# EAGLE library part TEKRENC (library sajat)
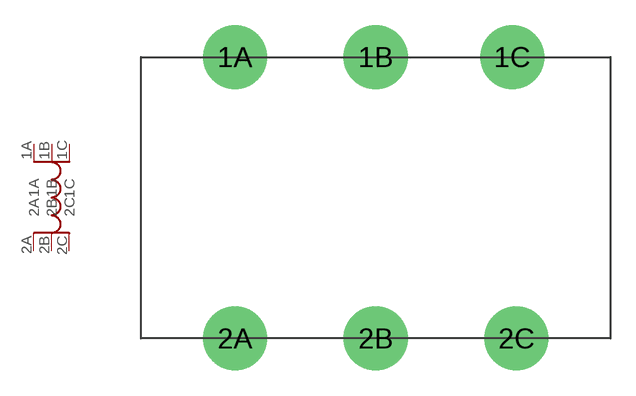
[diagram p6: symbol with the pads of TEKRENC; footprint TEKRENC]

Designator prefix -

## TEKRENC  [TEKRENC]
1A  1A
1B  1B
1C  1C
2A  2A
2B  2B
2C  2C

## Footprint TEKRENC (pad centres in mm)
drill 1 pad 3.81 round: 1A -8.382,8.382; 1B 0,8.382; 1C 8.128,8.382; 2A -8.382,-8.382; 2B 0,-8.382; 2C 8.382,-8.382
